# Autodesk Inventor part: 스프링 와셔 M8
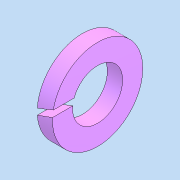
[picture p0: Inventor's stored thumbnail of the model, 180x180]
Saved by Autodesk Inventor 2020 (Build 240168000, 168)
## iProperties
Created: 2024-11
Part Number: 스프링 와셔 M8
Material: 강철, 연강
Description: 스프링 잠금 와셔
Document SubType Name: Modeling
Designer: 1강의실14
Density: 7.85 g/cm^3
Appearance: 기본값
Author: jhkim
Sending System: Autodesk Inventor 2025
Preprocessor: ST-DEVELOPER v20
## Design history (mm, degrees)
node "스프링 와셔 M81"
node "솔리드1"
body "Solid1"
